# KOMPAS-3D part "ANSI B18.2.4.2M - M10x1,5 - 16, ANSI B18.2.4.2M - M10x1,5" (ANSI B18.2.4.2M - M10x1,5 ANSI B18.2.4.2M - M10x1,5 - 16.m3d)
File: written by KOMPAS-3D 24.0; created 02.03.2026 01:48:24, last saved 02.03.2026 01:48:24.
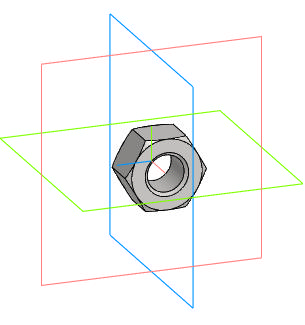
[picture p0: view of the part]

Document properties: Автор: R2D2; Полное имя файла: E:\Работа\Зайцев\GVWR3131M-2W-F-S Задвижка клиновая с выдвижным штоком DN.ru Ду50-200 Ру63\DN150\исходные материалы\ANSI B18.2.4.2M - M10x1,5 ANSI B18.2.4.2M - M10x1,5 - 16.m3d

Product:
- Body: Solid1  | qty 1
- Part/product: ANSI B18.2.4.2M - M10x1,5 - 16  | designation ANSI B18.2.4.2M - M10x1,5
    Комментарий: Типы метрических   шестигранных гаек   2
    additional columns: Сталь, мягкая

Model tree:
1. Solid1  (labels: Solid1)

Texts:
  ANSI B18.2.4.2M - M10x1,5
